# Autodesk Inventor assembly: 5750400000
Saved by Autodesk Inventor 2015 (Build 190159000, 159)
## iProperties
Created: 2020-07
Part Number: 5750400000
Checked By: TraceParts S.A.
Catalog Web Link: www.traceparts.com
Document SubType Name: Assembly
Designer: TraceParts
Company: TraceParts S.A.
Author: TraceParts
REFERENCE: 5750400000
DESIGN: HXBR-300 ECOWATT (230V50/60HZ) V5 - 5750400000
SUPPLIER: Soler & Palau
TraceParts.PartNumber: 10-20122018-119605
TraceParts.PartTitle: HXBR-ECOWATT
TraceParts.InstanceId: 10-20122018-1196059WMZYER4BPWL436CNJXHIM60O
TraceParts.PartStatus: Published
TraceParts.PartVersion: 1.0.2
TRACEPARTS: TRACEPARTS
TraceParts.PartLanguage: en
TraceParts.ClassPath: SOLER_PALAU:10-20122018-119605
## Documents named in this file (3)
- C:\TPO v2\SharedFS\Outgoing\5750400000.iam
- C:\TPO v2\SharedFS\Outgoing\5750400000_01.ipt
- C:\TPO v2\SharedFS\Outgoing\5750400000_02.ipt
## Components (2 placed, 2 different names)
1. 5750400000_01:1
2. 5750400000_02:1
